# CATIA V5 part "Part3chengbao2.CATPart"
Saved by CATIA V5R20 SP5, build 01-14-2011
Part number: Part3chengbao2
Bounding box of the stored display mesh (mm): x -81 to 81, y -81 to 81, z -60 to 226
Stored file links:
  C:\Documents and Settings\Student\桌面\Part3chengbao2.CATPart
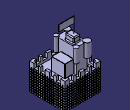
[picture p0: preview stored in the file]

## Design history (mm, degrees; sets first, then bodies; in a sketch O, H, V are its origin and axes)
Body1 (main body)
  Sketch1 on xy-plane, origin (0, 0, 0), H (1, 0, 0), V (0, 1, 0)
    line L1 (80, 80) -> (80, -80)
    line L2 (80, -80) -> (-80, -80)
    line L3 (-80, -80) -> (-80, 80)
    line L4 (-80, 80) -> (80, 80)
    vertical: L1 V, L3 V
    horizontal: L2 H, L4 H
    equidistance: L1 L3 O, L2 L4 O
  Pad1: profile Sketch1, direction (0, 0, 1), length 60, mirrored extent
  Sketch2 on end face of Pad1, origin (0, 0, 60), H (1, 0, 0), V (0, 1, 0)
    line L1 (70, 70) -> (70, -70)
    line L2 (70, -70) -> (-70, -70)
    line L3 (-70, -70) -> (-70, 70)
    line L4 (-70, 70) -> (70, 70)
    length L1 = 140
    vertical: L1 V, L3 V
    horizontal: L2 H, L4 H
    equidistance: L1 L3 O, L2 L4 O
  Pocket1: profile Sketch2, direction (0, 0, -1), length 30
  Sketch3 on face of Pad1 from Sketch1.L1, origin (80, 0, 0), H (0, 1, 0), V (0, 0, 1)
    point P1 (-50, 60)
    line L1 (-40, 80) -> (-40, 40)
    line L2 (-40, 40) -> (-60, 40)
    line L3 (-60, 40) -> (-60, 80)
    line L4 (-60, 80) -> (-40, 80)
    vertical: L1 V, L3 V
    horizontal: L2 H, L4 H
    equidistance: L1 L3 P1, L2 L4 P1
  Pocket2: profile Sketch3, direction (-1, 0, 0), length 30
  Sketch4 on face of Pad1 from Sketch1.L1, origin (80, 0, 0), H (0, 1, 0), V (0, 0, 1)
    point P1 (-20, 50)
    line L1 (-10, 60) -> (-10, 40)
    line L2 (-10, 40) -> (-30, 40)
    line L3 (-30, 40) -> (-30, 60)
    line L4 (-30, 60) -> (-10, 60)
    vertical: L1 V, L3 V
    horizontal: L2 H, L4 H
    equidistance: L1 L3 P1, L2 L4 P1
  Pocket3: profile Sketch4, direction (-1, 0, 0), length 30
  Sketch5 on face of Pad1 from Sketch1.L1, origin (80, 0, 0), H (0, 1, 0), V (0, 0, 1)
    point P1 (20, 50)
    line L1 (30, 60) -> (30, 40)
    line L2 (30, 40) -> (10, 40)
    line L3 (10, 40) -> (10, 60)
    line L4 (10, 60) -> (30, 60)
    vertical: L1 V, L3 V
    horizontal: L2 H, L4 H
    equidistance: L1 L3 P1, L2 L4 P1
  Pocket4: profile Sketch5, direction (-1, 0, 0), length 30
  Sketch6 on face of Pad1 from Sketch1.L1, origin (80, 0, 0), H (0, 1, 0), V (0, 0, 1)
    point P1 (50, 50)
    line L1 (60, 60) -> (60, 40)
    line L2 (60, 40) -> (40, 40)
    line L3 (40, 40) -> (40, 60)
    line L4 (40, 60) -> (60, 60)
    vertical: L1 V, L3 V
    horizontal: L2 H, L4 H
    equidistance: L1 L3 P1, L2 L4 P1
  Pocket5: profile Sketch6, direction (-1, 0, 0), length 30
  Sketch7 on face of Pad1 from Sketch1.L4, origin (0, 80, 0), H (-1, 0, 0), V (0, 0, 1)
    point P1 (-50, 50)
    line L1 (-40, 60) -> (-40, 40)
    line L2 (-40, 40) -> (-60, 40)
    line L3 (-60, 40) -> (-60, 60)
    line L4 (-60, 60) -> (-40, 60)
    vertical: L1 V, L3 V
    horizontal: L2 H, L4 H
    equidistance: L1 L3 P1, L2 L4 P1
  Pocket6: profile Sketch7, direction (0, -1, 0), length 30
  Sketch8 on face of Pad1 from Sketch1.L4, origin (0, 80, 0), H (-1, 0, 0), V (0, 0, 1)
    point P1 (-20, 50)
    line L1 (-10, 60) -> (-10, 40)
    line L2 (-10, 40) -> (-30, 40)
    line L3 (-30, 40) -> (-30, 60)
    line L4 (-30, 60) -> (-10, 60)
    vertical: L1 V, L3 V
    horizontal: L2 H, L4 H
    equidistance: L1 L3 P1, L2 L4 P1
  Pocket7: profile Sketch8, direction (0, -1, 0), length 30
  Sketch9 on face of Pad1 from Sketch1.L4, origin (0, 80, 0), H (-1, 0, 0), V (0, 0, 1)
    point P1 (20, 50)
    line L1 (30, 60) -> (30, 40)
    line L2 (30, 40) -> (10, 40)
    line L3 (10, 40) -> (10, 60)
    line L4 (10, 60) -> (30, 60)
    vertical: L1 V, L3 V
    horizontal: L2 H, L4 H
    equidistance: L1 L3 P1, L2 L4 P1
  Pocket8: profile Sketch9, direction (0, -1, 0), length 30
  Sketch10 on face of Pad1 from Sketch1.L4, origin (0, 80, 0), H (-1, 0, 0), V (0, 0, 1)
    point P1 (50, 50)
    line L1 (60, 60) -> (60, 40)
    line L2 (60, 40) -> (40, 40)
    line L3 (40, 40) -> (40, 60)
    line L4 (40, 60) -> (60, 60)
    vertical: L1 V, L3 V
    horizontal: L2 H, L4 H
    equidistance: L1 L3 P1, L2 L4 P1
  Pocket9: profile Sketch10, direction (0, -1, 0), length 30
  Sketch11 on face of Pad1 from Sketch1.L3, origin (-80, 0, 0), H (0, -1, 0), V (0, 0, 1)
    point P1 (-50, 50)
    line L1 (-40, 60) -> (-40, 40)
    line L2 (-40, 40) -> (-60, 40)
    line L3 (-60, 40) -> (-60, 60)
    line L4 (-60, 60) -> (-40, 60)
    vertical: L1 V, L3 V
    horizontal: L2 H, L4 H
    equidistance: L1 L3 P1, L2 L4 P1
  Pocket10: profile Sketch11, direction (1, 0, 0), length 30
  Sketch12 on face of Pad1 from Sketch1.L3, origin (-80, 0, 0), H (0, -1, 0), V (0, 0, 1)
    point P1 (-20, 50)
    line L1 (-10, 60) -> (-10, 40)
    line L2 (-10, 40) -> (-30, 40)
    line L3 (-30, 40) -> (-30, 60)
    line L4 (-30, 60) -> (-10, 60)
    vertical: L1 V, L3 V
    horizontal: L2 H, L4 H
    equidistance: L1 L3 P1, L2 L4 P1
  Pocket11: profile Sketch12, direction (1, 0, 0), length 30
  Sketch13 on face of Pad1 from Sketch1.L3, origin (-80, 0, 0), H (0, -1, 0), V (0, 0, 1)
    point P1 (20, 50)
    line L1 (30, 60) -> (30, 40)
    line L2 (30, 40) -> (10, 40)
    line L3 (10, 40) -> (10, 60)
    line L4 (10, 60) -> (30, 60)
    vertical: L1 V, L3 V
    horizontal: L2 H, L4 H
    equidistance: L1 L3 P1, L2 L4 P1
  Pocket12: profile Sketch13, direction (1, 0, 0), length 30
  Sketch14 on face of Pad1 from Sketch1.L3, origin (-80, 0, 0), H (0, -1, 0), V (0, 0, 1)
    point P1 (50, 50)
    line L1 (60, 60) -> (60, 40)
    line L2 (60, 40) -> (40, 40)
    line L3 (40, 40) -> (40, 60)
    line L4 (40, 60) -> (60, 60)
    vertical: L1 V, L3 V
    horizontal: L2 H, L4 H
    equidistance: L1 L3 P1, L2 L4 P1
  Pocket13: profile Sketch14, direction (1, 0, 0), length 30
  Sketch15 on face of Pad1 from Sketch1.L2, origin (0, -80, 0), H (1, 0, 0), V (0, 0, 1)
    point P1 (-50, 50)
    line L1 (-40, 60) -> (-40, 40)
    line L2 (-40, 40) -> (-60, 40)
    line L3 (-60, 40) -> (-60, 60)
    line L4 (-60, 60) -> (-40, 60)
    point P6 (-20, 50)
    line L5 (-10, 60) -> (-10, 40)
    line L6 (-10, 40) -> (-30, 40)
    line L7 (-30, 40) -> (-30, 60)
    line L8 (-30, 60) -> (-10, 60)
    point P11 (20, 50)
    line L9 (30, 60) -> (30, 40)
    line L10 (30, 40) -> (10, 40)
    line L11 (10, 40) -> (10, 60)
    line L12 (10, 60) -> (30, 60)
    point P16 (50, 50)
    line L13 (60, 60) -> (60, 40)
    line L14 (60, 40) -> (40, 40)
    line L15 (40, 40) -> (40, 60)
    line L16 (40, 60) -> (60, 60)
    vertical: L1 V, L3 V, L5 V, L7 V, L9 V, L11 V, L13 V, L15 V
    horizontal: L2 H, L4 H, L6 H, L8 H, L10 H, L12 H, L14 H, L16 H
    equidistance: L1 L3 P1, L2 L4 P1, L5 L7 P6, L6 L8 P6, L9 L11 P11, L10 L12 P11, L13 L15 P16, L14 L16 P16
  Pocket14: profile Sketch15, direction (0, 1, 0), length 30
  Sketch16 on end face of Pocket1, origin (0, 0, 30), H (1, 0, 0), V (0, 1, 0)
    line L1 (-50, 50) -> (0, 50)
    line L2 (0, 50) -> (0, -40)
    line L3 (0, -40) -> (-50, -40)
    line L4 (-50, -40) -> (-50, 50)
    horizontal: L1 H, L3 H
    vertical: L2 V, L4 V
  Pad2: profile Sketch16, direction (0, 0, 1), length 106
  Sketch17 on end face of Pocket1, origin (0, 0, 30), H (1, 0, 0), V (0, 1, 0)
    line L1 (40, 40) -> (0, 40)
    line L2 (0, 40) -> (0, -20)
    line L3 (0, -20) -> (40, -20)
    line L4 (40, -20) -> (40, 40)
    horizontal: L1 H, L3 H
    vertical: L2 V, L4 V
  Pad3: profile Sketch17, direction (0, 0, 1), length 57
  Point1: type OnCurve, Support edge [face of Pad2 from Sketch16.L3 | face of Pad2 from Sketch16.L4], Length 80
  Point2: type OnCurve, Support edge [face of Pad2 from Sketch16.L2 | face of Pad2 from Sketch16.L3], Length 80
  Point3: type OnCurve, Support edge [face of Pad2 from Sketch16.L4 | face of Pad2 from Sketch16.L1], Length 80
  Plane1: type 3Points, Element1 Point1, Element2 Point2, Element3 Point3
  Sketch18 on Plane1, origin (0, 0, 110), H (1, 0, 0), V (0, 1, 0)
    circle A1 centre (-50, -40) radius 13
    radius A1 = 13
  Pad4: profile Sketch18, direction (0, 0, 1), length 31, mirrored extent
  Plane2: type Offset, RefPlane Plane1, Offset 58
  Plane3: type Offset, RefPlane Plane2, Offset -27
  Sketch19 on Plane2, origin (0, 0, 168), H (1, 0, 0), V (0, 1, 0)
    point P1 (-50, -40)
  Point4: type OnPlane, Support Plane2, H -48.123, V -41.996, Direction (1, 0, 0)
  Point5: type OnPlane, Support Plane2, H -47.917, V -37.936, Direction (1, 0, 0)
  Point6: type OnPlane, Support Plane2, H -52.385, V -37.915, Direction (1, 0, 0)
  Sketch20 on face of Pad2 from Sketch16.L4, origin (-50, 0, 0), H (0, -1, 0), V (0, 0, 1)
    point P1 (-20, 110)
    line L1 (-10, 130) -> (-10, 90)
    line L2 (-10, 90) -> (-30, 90)
    line L3 (-30, 90) -> (-30, 130)
    line L4 (-30, 130) -> (-10, 130)
    vertical: L1 V, L3 V
    horizontal: L2 H, L4 H
    equidistance: L1 L3 P1, L2 L4 P1
  Pad5: profile Sketch20, direction (-1, 0, 0), length 6, mirrored extent, thin wall 1
  Sketch21 on face of Pad2 from Sketch16.L4, origin (-50, 0, 0), H (0, -1, 0), V (0, 0, 1)
    line L1 (0, 130) -> (20, 130)
    line L2 (20, 130) -> (20, 90)
    line L3 (20, 90) -> (0, 90)
    line L4 (0, 90) -> (0, 130)
    horizontal: L1 H, L3 H
    vertical: L2 V, L4 V
  Pad6: profile Sketch21, direction (-1, 0, 0), length 6, thin wall 1
  Sketch22 on face of Pad2 from Sketch16.L4, origin (-50, 0, 0), H (0, -1, 0), V (0, 0, 1)
    line L1 (-30, 110) -> (-10, 110)
    horizontal: L1 H
  Pad7: profile Sketch22, direction (-1, 0, 0), length 6, thin wall 2, second thickness 2
  Sketch23 on face of Pad2 from Sketch16.L4, origin (-50, 0, 0), H (0, -1, 0), V (0, 0, 1)
    line L1 (-20, 130) -> (-20, 90)
    vertical: L1 V
  Pad8: profile Sketch23, direction (-1, 0, 0), length 6, thin wall 2, second thickness 2
  Sketch24 on face of Pad2 from Sketch16.L4, origin (-50, 0, 0), H (0, -1, 0), V (0, 0, 1)
    line L1 (0, 110) -> (20, 110)
    point P1 (0, 110)
    coincidence: P1 V
    horizontal: L1 H
  Pad9: profile Sketch24, direction (-1, 0, 0), length 6, thin wall 2, second thickness 2
  Sketch25 on face of Pad2 from Sketch16.L4, origin (-50, 0, 0), H (0, -1, 0), V (0, 0, 1)
    line L1 (10, 130) -> (10, 90)
    vertical: L1 V
  Pad10: profile Sketch25, direction (-1, 0, 0), length 6, thin wall 2, second thickness 2
  Sketch26 on face of Pad1 from Sketch1.L3, origin (-80, 0, 0), H (0, -1, 0), V (0, 0, 1)
    line L1 (-80, 30) -> (80, 30)
    line L2 (-80, 20) -> (80, 20)
    line L3 (-80, 10) -> (80, 10)
    line L4 (-80, 0) -> (80, 0)
    line L5 (-80, -10) -> (80, -10)
    line L6 (-80, -20) -> (80, -20)
    line L7 (-80, -30) -> (80, -30)
    line L8 (-80, -40) -> (80, -40)
    line L9 (-80, -50) -> (80, -50)
    line L10 (-70, 40) -> (-70, -60)
    line L11 (-60, 40) -> (-60, -60)
    line L12 (-50, 40) -> (-50, -60)
    line L13 (-40, 40) -> (-40, -60)
    line L14 (-30, 40) -> (-30, -60)
    line L15 (-20, 40) -> (-20, -60)
    line L16 (-10, 40) -> (-10, -60)
    line L17 (0, 40) -> (0, -60)
    point P33 (0, 40)
    line L18 (10, 40) -> (10, -60)
    line L19 (20, 40) -> (20, -60)
    line L20 (30, 40) -> (30, -60)
    line L21 (40, 40) -> (40, -60)
    line L22 (50, 40) -> (50, -60)
    line L23 (60, 40) -> (60, -60)
    line L24 (70, 40) -> (70, -60)
    horizontal: L1 H, L2 H, L3 H, L4 H, L5 H, L6 H, L7 H, L8 H, L9 H
    vertical: L10 V, L11 V, L12 V, L13 V, L14 V, L15 V, L16 V, L17 V, L18 V, L19 V, L20 V, L21 V, L22 V, L23 V, L24 V
    coincidence: P33 V
  Pad11: profile Sketch26, direction (-1, 0, 0), length 1, thin wall 1, second thickness 1
  Sketch27 on face of Pad11, origin (0, -80, 0), H (1, 0, 0), V (0, 0, 1)
    line L1 (-80, 30) -> (80, 30)
    line L2 (-80, 20) -> (80, 20)
    line L3 (-80, 10) -> (80, 10)
    line L4 (-80, 0) -> (80, 0)
    line L5 (-80, -10) -> (80, -10)
    line L6 (-80, -20) -> (80, -20)
    line L7 (-80, -30) -> (80, -30)
    line L8 (-80, -40) -> (80, -40)
    line L9 (-80, -50) -> (80, -50)
    line L10 (-70, 40) -> (-70, -60)
    line L11 (-60, 40) -> (-60, -60)
    line L12 (-50, 40) -> (-50, -60)
    line L13 (-40, 40) -> (-40, -60)
    line L14 (-30, 40) -> (-30, -60)
    line L15 (-20, 40) -> (-20, -60)
    line L16 (-10, 40) -> (-10, -60)
    line L17 (0, 40) -> (0, -60)
    point P33 (0, 40)
    line L18 (10, 40) -> (10, -60)
    line L19 (20, 40) -> (20, -60)
    line L20 (30, 40) -> (30, -60)
    line L21 (40, 40) -> (40, -60)
    line L22 (50, 40) -> (50, -60)
    line L23 (60, 40) -> (60, -60)
    line L24 (70, 40) -> (70, -60)
    horizontal: L1 H, L2 H, L3 H, L4 H, L5 H, L6 H, L7 H, L8 H, L9 H
    vertical: L10 V, L11 V, L12 V, L13 V, L14 V, L15 V, L16 V, L17 V, L18 V, L19 V, L20 V, L21 V, L22 V, L23 V, L24 V
    coincidence: P33 V
  Pad12: profile Sketch27, direction (0, -1, 0), length 1, thin wall 1, second thickness 1
  Sketch28 on face of Pad11, origin (0, 80, 0), H (-1, 0, 0), V (0, 0, 1)
    line L1 (-80, 30) -> (80, 30)
    line L2 (-80, 20) -> (80, 20)
    line L3 (-80, 10) -> (80, 10)
    line L4 (-80, 0) -> (80, 0)
    point P7 (-80, 0)
    line L5 (-80, -10) -> (80, -10)
    line L6 (-80, -20) -> (80, -20)
    line L7 (-80, -30) -> (80, -30)
    line L8 (-80, -40) -> (80, -40)
    line L9 (-80, -50) -> (80, -50)
    line L10 (-70, 40) -> (-70, -60)
    line L11 (-60, 40) -> (-60, -60)
    line L12 (-50, 40) -> (-50, -60)
    line L13 (-40, 40) -> (-40, -60)
    line L14 (-30, 40) -> (-30, -60)
    line L15 (-20, 40) -> (-20, -60)
    line L16 (-10, 40) -> (-10, -60)
    line L17 (0, 40) -> (0, -60)
    point P33 (0, 40)
    line L18 (10, 40) -> (10, -60)
    line L19 (20, 40) -> (20, -60)
    line L20 (30, 40) -> (30, -60)
    line L21 (40, 40) -> (40, -60)
    line L22 (50, 40) -> (50, -60)
    line L23 (60, 40) -> (60, -60)
    line L24 (70, 40) -> (70, -60)
    horizontal: L1 H, L2 H, L3 H, L4 H, L5 H, L6 H, L7 H, L8 H, L9 H
    coincidence: P7 H, P33 V
    vertical: L10 V, L11 V, L12 V, L13 V, L14 V, L15 V, L16 V, L17 V, L18 V, L19 V, L20 V, L21 V, L22 V, L23 V, L24 V
  Pad13: profile Sketch28, direction (0, 1, 0), length 1, thin wall 1, second thickness 1
  Fillet1: radius 5, on edge [face of Pad13 | face of Pad1 from Sketch1.L3]
  Fillet2: radius 1, on end face of Pad3; face of Pad3 from Sketch17.L1
  Sketch29 on end face of Pad2, origin (0, 0, 136), H (1, 0, 0), V (0, 1, 0)
    line L1 (-40, 30) -> (-10, 30)
    line L2 (-10, 30) -> (-10, -10)
    line L3 (-10, -10) -> (-40, -10)
    line L4 (-40, -10) -> (-40, 30)
    horizontal: L1 H, L3 H
    vertical: L2 V, L4 V
  Pad14: profile Sketch29, direction (0, 0, 1), length 23
  Fillet3: radius 4, on face of Pad14 from Sketch29.L2; end face of Pad14; edge [face of Pad14 from Sketch29.L3 | face of Pad14 from Sketch29.L4]; face of Pad14 from Sketch29.L1; face of Pad14 from Sketch29.L4
  Sketch30 on face of Pad13, origin (80, 0, 0), H (0, 1, 0), V (0, 0, 1)
    line L1 (-80, 30) -> (80, 30)
    line L2 (-80, 20) -> (80, 20)
    line L3 (-80, 10) -> (80, 10)
    line L4 (-80, 0) -> (80, 0)
    line L5 (-80, -10) -> (80, -10)
    line L6 (-80, -20) -> (80, -20)
    line L7 (-80, -30) -> (80, -30)
    line L8 (-80, -40) -> (80, -40)
    line L9 (-80, -50) -> (80, -50)
    line L10 (-70, 40) -> (-70, -60)
    line L11 (-60, 40) -> (-60, -60)
    line L12 (-50, 40) -> (-50, -60)
    line L13 (-40, 40) -> (-40, -60)
    line L14 (-30, 40) -> (-30, -60)
    line L15 (-20, 40) -> (-20, -60)
    line L16 (-10, 40) -> (-10, -60)
    line L17 (0, 40) -> (0, -60)
    point P33 (0, 40)
    line L18 (10, 40) -> (10, -60)
    line L19 (20, 40) -> (20, -50)
    line L20 (20, -50) -> (20, -60)
    line L21 (30, 40) -> (30, -60)
    line L22 (40, 40) -> (40, -60)
    line L23 (50, 40) -> (50, -60)
    line L24 (60, 40) -> (60, -60)
    line L25 (70, 40) -> (70, -60)
    horizontal: L1 H, L2 H, L3 H, L4 H, L5 H, L6 H, L7 H, L8 H, L9 H
    vertical: L10 V, L11 V, L12 V, L13 V, L14 V, L15 V, L16 V, L17 V, L18 V, L19 V, L20 V, L21 V, L22 V, L23 V, L24 V, L25 V
    coincidence: P33 V
  Pad15: profile Sketch30, direction (1, 0, 0), length 1, thin wall 1, second thickness 1
  Plane4: type 3Points, Element1 Point2, Element2 Point1, Element3 Point3
  Sketch31 on Plane4, origin (0, 0, 110), H (1, 0, 0), V (0, -1, 0)
    circle A1 centre (0, 40) radius 10
    point P1 (0, 40)
    coincidence: P1 V
  Pad16: profile Sketch31, direction (0, 0, -1), length 31, mirrored extent
  Sketch32 on end face of Pad4, origin (0, 0, 141), H (1, 0, 0), V (0, 1, 0)
    reference projected circle E1 centre (0, -40) radius 10 from edge [start face of Pad16 | face of Pad16 from Sketch31.A1]
    reference projected circle E2 centre (-50, -40) radius 13 from edge [face of Pad4 from Sketch18.A1 | end face of Pad4]
    radius E1 = 10 (reference)
    radius E2 = 13 (reference)
  Plane5: type 3Points, Element1 Point3, Element2 Point1, Element3 Point2
  Point7: type OnCurve, Support edge [face of Pad2 from Sketch16.L1 | face of Pad2 from Sketch16.L2], Length 80
  Plane6: type 3Points, Element1 Point7, Element2 Point3, Element3 Point2
  Sketch33 on Plane6, origin (0, 0, 110), H (1, 0, 0), V (0, 1, 0)
    circle A1 centre (-50, 50) radius 14.1421
    circle A2 centre (0, 50) radius 10
    point P2 (0, 50)
    coincidence: P2 V
  Pad17: profile Sketch33, direction (0, 0, 1), length 30, mirrored extent
  Point8: type OnPlane, Support end face of Pad14, H -23.494, V 9.823, Direction (1, 0, 0)
  Plane7: type OffsetPt, RefPlane xy-plane, RefPoint Point8
  Sketch34 on end face of Pad14, origin (0, 0, 159), H (1, 0, 0), V (0, 1, 0)
    circle A1 centre (-30, 10) radius 2
    radius A1 = 2
  Pad18: profile Sketch34, direction (0, 0, 1), length 56
  Point9: type OnCurve, Support edge [face of Pad18 from Sketch34.A1 | end face of Pad18], RefPoint {extremum Reference edge [face of Pad18 from Sketch34.A1 | end face of Pad18], Direction (1, 2, 3)}, Length 7.21
  Point10: type OnSurface, Support face of Pad18 from Sketch34.A1, Length 11.62, Direction (0.0127, 0.0005, 0.9999)
  Line1: type PtPt, FirstPoint Point9, SecondPoint Point10
  Plane8: type Offset, RefPlane Plane7, Offset 53
  Plane9: type Offset, RefPlane Plane7, Offset 37
  Sketch35 on Plane8, origin (0, 0, 212), H (1, 0, 0), V (0, 1, 0)
    line L1 (-30, 12) -> (40, 12)
    line L2 (40, 12) -> (40, 10)
    line L3 (40, 10) -> (-30, 10)
    line L4 (-30, 10) -> (-30, 12)
    length L2 = 2
    horizontal: L1 H, L3 H
    vertical: L2 V, L4 V
  Pad19: profile Sketch35, direction (0, 0, 1), length 14, mirrored extent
